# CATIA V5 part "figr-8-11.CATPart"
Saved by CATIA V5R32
Part number: Part2
Bounding box of the stored display mesh (mm): x -37.886 to 37.886, y -61.415 to 61.415, z 29 to 58
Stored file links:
  D:\PROJECTS\Project 2022\CATIA V5 6R 2022\Resources\Part Files\c08_catia_v5_6r2022_prt\figr-8-11.CATPart
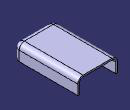
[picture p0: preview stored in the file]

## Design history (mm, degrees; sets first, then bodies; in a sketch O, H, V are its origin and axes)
Body1 (main body)
  Sketch1 on xy-plane, origin (0, 0, 0), H (1, 0, 0), V (0, 1, 0)
    line L1 (37.8862, 61.4155) -> (37.8862, -61.4155)
    line L2 (37.8862, -61.4155) -> (-37.8862, -61.4155)
    line L3 (-37.8862, -61.4155) -> (-37.8862, 61.4155)
    line L4 (-37.8862, 61.4155) -> (37.8862, 61.4155)
    vertical: L1 V, L3 V
    horizontal: L2 H, L4 H
    equidistance: L1 L3 O, L2 L4 O
  Pad1: profile Sketch1, direction (0, 0, 1), length 29
  Fillet1: radius 10, on edge [face of Pad1 | face of Pad1] (x5)
  Shell1: ExtOffset 0, Face (face of Pad1; face of Pad1), IntOffset 3
  Symmetry1: Reference face of Pad1, ToTransfor Shell1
